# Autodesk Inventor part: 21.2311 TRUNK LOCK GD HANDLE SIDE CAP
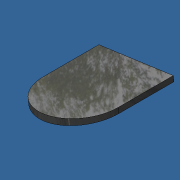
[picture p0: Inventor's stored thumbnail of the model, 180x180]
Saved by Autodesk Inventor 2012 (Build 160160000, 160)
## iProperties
Created: 2014-09
Part Number: 21.2311 TRUNK LOCK GD HANDLE SIDE CAP
Material: ABS Plastic
Document SubType Name: Modeling
Designer: Admin
Density: 1.06 g/cm^3
Mass: 0.309022 g
Surface Area: 5.72137 cm^2
Volume: 0.29153 cm^3
Author: Admin
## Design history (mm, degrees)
feature "Base1"
body "Solid1"
